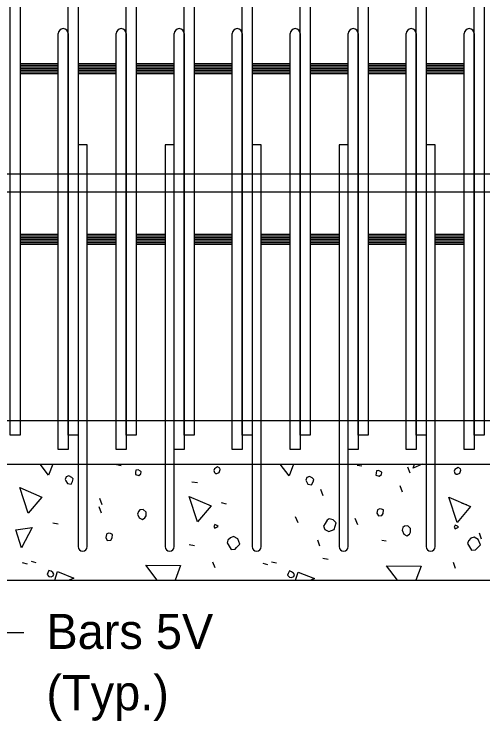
# Model space of a CAD drawing. Extents: x 120588.1 to 120659.6, y 120683.4 to 120715.5.
# Drawn here: x 120592.421 to 120595.115, y 120694.946 to 120699.004 of the extents above; entities that cross this region are included whole.
import ezdxf

# ---------------------------------------------------------------- set-up
doc = ezdxf.new("R2010")
doc.units = 0
for name, color, linetype in [('Dimension', 7, 'Continuous'), ('SheetBorder_dp', 7, 'Continuous'), ('SheetLines_dp', 7, 'Continuous'), ('SupstrConc', 7, 'Continuous')]:
    doc.layers.add(name, color=color, linetype=linetype)

msp = doc.modelspace()

# ---------------------------------------------------------------- linework, layer by layer
at = {"layer": 'Dimension'}
for p, q in [((120593.0102, 120696.4184), (120593.0367, 120696.4131)), ((120594.3926, 120696.4148), (120594.4191, 120696.4095)), ((120594.6966, 120696.3689), (120594.6843, 120696.4024)), ((120593.4433, 120696.3176), (120593.4751, 120696.3141)), ((120594.1979, 120696.2387), (120594.1837, 120696.2741)), ((120594.6542, 120696.2593), (120594.6401, 120696.2946)), ((120592.9271, 120696.1868), (120592.913, 120696.2221)), ((120593.6112, 120696.1992), (120593.6395, 120696.1921)), ((120594.9936, 120696.1956), (120595.0219, 120696.1885)), ((120592.924, 120696.1389), (120592.9099, 120696.1743)), ((120594.0532, 120696.0825), (120594.039, 120696.1178)), ((120594.3961, 120696.0719), (120594.382, 120696.1072)), ((120592.6442, 120696.0831), (120592.6742, 120696.0778)), ((120595.1079, 120695.99), (120595.0956, 120696.0236)), ((120594.1787, 120695.9499), (120594.1663, 120695.9835)), ((120594.534, 120695.9835), (120594.5588, 120695.9799)), ((120593.4274, 120695.9587), (120593.4574, 120695.9534)), ((120592.5188, 120695.8633), (120592.547, 120695.8562)), ((120594.1964, 120695.8792), (120594.2264, 120695.8739)), ((120592.4675, 120695.8544), (120592.4958, 120695.8474)), ((120593.5759, 120695.8244), (120593.5635, 120695.858)), ((120593.8499, 120695.8509), (120593.8782, 120695.8438)), ((120593.9012, 120695.8597), (120593.9294, 120695.8527)), ((120594.9583, 120695.8208), (120594.9459, 120695.8544))]:
    msp.add_line(p, q, dxfattribs=at)
for points in [[(120592.6195, 120696.3565), (120592.571, 120696.4203)], [(120592.6434, 120696.4203), (120592.6195, 120696.3565)], [(120593.5794, 120696.3653), (120593.5865, 120696.3653), (120593.6006, 120696.3724), (120593.6059, 120696.3883), (120593.6042, 120696.3971), (120593.59, 120696.4042), (120593.5723, 120696.3936), (120593.5688, 120696.383), (120593.5723, 120696.3724), (120593.5794, 120696.3653)], [(120594.0019, 120696.3529), (120593.9507, 120696.4203)], [(120594.0271, 120696.4203), (120594.0019, 120696.3529)], [(120594.7143, 120696.3971), (120594.7215, 120696.4203)], [(120594.766, 120696.4203), (120594.7143, 120696.3971)], [(120594.9618, 120696.3618), (120594.9689, 120696.3618), (120594.983, 120696.3689), (120594.9883, 120696.3848), (120594.9866, 120696.3936), (120594.9724, 120696.4007), (120594.9547, 120696.3901), (120594.9512, 120696.3795), (120594.9547, 120696.3689), (120594.9618, 120696.3618)], [(120592.7185, 120696.3247), (120592.7274, 120696.3088), (120592.7486, 120696.3052), (120592.7574, 120696.3211), (120592.7609, 120696.3353), (120592.7521, 120696.3441), (120592.7362, 120696.3529), (120592.7203, 120696.3476), (120592.715, 120696.3317), (120592.7185, 120696.3247)], [(120593.118, 120696.36), (120593.1375, 120696.3547), (120593.1499, 120696.3636), (120593.1516, 120696.3759), (120593.1481, 120696.3795), (120593.1339, 120696.3865), (120593.1216, 120696.3848), (120593.1198, 120696.3724), (120593.118, 120696.36)], [(120594.1009, 120696.3211), (120594.1097, 120696.3052), (120594.131, 120696.3017), (120594.1398, 120696.3176), (120594.1433, 120696.3317), (120594.1345, 120696.3406), (120594.1186, 120696.3494), (120594.1027, 120696.3441), (120594.0974, 120696.3282), (120594.1009, 120696.3211)], [(120594.5004, 120696.3565), (120594.5199, 120696.3512), (120594.5322, 120696.36), (120594.534, 120696.3724), (120594.5305, 120696.3759), (120594.5163, 120696.383), (120594.504, 120696.3812), (120594.5022, 120696.3689), (120594.5004, 120696.3565)], [(120592.5022, 120696.1383), (120592.4544, 120696.285), (120592.5799, 120696.2302), (120592.5022, 120696.1383)], [(120593.4751, 120696.0878), (120593.4274, 120696.2345), (120593.5529, 120696.1797), (120593.4751, 120696.0878)], [(120594.9668, 120696.0842), (120594.919, 120696.231), (120595.0445, 120696.1762), (120594.9668, 120696.0842)], [(120593.1299, 120696.1331), (120593.1406, 120696.1119), (120593.1582, 120696.1012), (120593.1724, 120696.1119), (120593.1794, 120696.1225), (120593.1794, 120696.1437), (120593.1635, 120696.1596), (120593.1441, 120696.1578), (120593.1353, 120696.149), (120593.1299, 120696.1331)], [(120594.5057, 120696.139), (120594.5146, 120696.1231), (120594.534, 120696.1249), (120594.5429, 120696.1373), (120594.5446, 120696.1567), (120594.5322, 120696.162), (120594.5234, 120696.1638), (120594.5128, 120696.1603), (120594.5093, 120696.1567), (120594.5057, 120696.139)], [(120594.207, 120696.0454), (120594.23, 120696.033), (120594.26, 120696.0454), (120594.2724, 120696.0825), (120594.2547, 120696.1002), (120594.2317, 120696.1055), (120594.2211, 120696.0984), (120594.2087, 120696.0789), (120594.1999, 120696.063), (120594.207, 120696.0454)], [(120593.5741, 120696.0524), (120593.5936, 120696.0613), (120593.5865, 120696.0683), (120593.5741, 120696.0736), (120593.5688, 120696.0613), (120593.5741, 120696.0524)], [(120594.6507, 120696.0401), (120594.6613, 120696.0188), (120594.679, 120696.0082), (120594.6931, 120696.0188), (120594.7002, 120696.0294), (120594.7002, 120696.0507), (120594.6843, 120696.0666), (120594.6648, 120696.0648), (120594.656, 120696.056), (120594.6507, 120696.0401)], [(120594.9565, 120696.0489), (120594.976, 120696.0577), (120594.9689, 120696.0648), (120594.9565, 120696.0701), (120594.9512, 120696.0577), (120594.9565, 120696.0489)], [(120592.464, 120695.9393), (120592.4304, 120696.0436), (120592.5241, 120696.056), (120592.464, 120695.9393)], [(120592.9479, 120695.9983), (120592.9568, 120695.9824), (120592.9762, 120695.9842), (120592.9851, 120695.9965), (120592.9868, 120696.016), (120592.9745, 120696.0213), (120592.9656, 120696.0231), (120592.955, 120696.0195), (120592.9515, 120696.016), (120592.9479, 120695.9983)], [(120593.6448, 120695.9676), (120593.6678, 120695.9305), (120593.6908, 120695.9322), (120593.6996, 120695.9411), (120593.7191, 120695.9605), (120593.7067, 120695.9906), (120593.6819, 120696.0047), (120593.6643, 120695.9976), (120593.6501, 120695.9835), (120593.6448, 120695.9676)], [(120595.0272, 120695.964), (120595.0502, 120695.9269), (120595.0732, 120695.9287), (120595.082, 120695.9375), (120595.1015, 120695.957), (120595.0891, 120695.987), (120595.0643, 120696.0012), (120595.0467, 120695.9941), (120595.0325, 120695.9799), (120595.0272, 120695.964)], [(120593.244, 120695.7537), (120593.1781, 120695.8403), (120593.3779, 120695.8385), (120593.3462, 120695.7537)], [(120594.6237, 120695.7537), (120594.5605, 120695.8368), (120594.7603, 120695.835), (120594.7299, 120695.7537)], [(120592.6213, 120695.7749), (120592.6337, 120695.7731), (120592.646, 120695.7784), (120592.6496, 120695.789), (120592.6443, 120695.7979), (120592.6337, 120695.8049), (120592.6213, 120695.8102), (120592.6142, 120695.7961), (120592.6107, 120695.7855), (120592.6213, 120695.7749)], [(120592.6556, 120695.7537), (120592.6708, 120695.8032), (120592.7645, 120695.766), (120592.7369, 120695.7537)], [(120594.0037, 120695.7714), (120594.0161, 120695.7696), (120594.0284, 120695.7749), (120594.032, 120695.7855), (120594.0267, 120695.7943), (120594.0161, 120695.8014), (120594.0037, 120695.8067), (120593.9966, 120695.7926), (120593.9931, 120695.782), (120594.0037, 120695.7714)], [(120594.039, 120695.7537), (120594.0532, 120695.7996), (120594.1469, 120695.7625), (120594.1272, 120695.7537)]]:
    msp.add_lwpolyline(points, dxfattribs=at)
at = {"layer": 'SheetBorder_dp'}
for p, q in [((120588.5208, 120698.087), (120598.0015, 120698.087)), ((120588.5208, 120697.9829), (120598.0015, 120697.9829)), ((120588.5208, 120696.6703), (120598.0015, 120696.6703)), ((120588.5208, 120696.4203), (120607.6672, 120696.4203)), ((120588.5208, 120695.7537), (120607.6672, 120695.7537))]:
    msp.add_line(p, q, dxfattribs=at)
at = {"layer": 'SheetLines_dp'}
msp.add_open_spline([(120592.4772, 120695.4523), (120592.2948, 120695.4435), (120592.0006, 120695.5358), (120592.1255, 120696.1436), (120591.3414, 120696.2866)], degree=2, dxfattribs=at)
at = {"layer": 'SupstrConc'}
for p, q in [((120592.6747, 120696.5037), (120592.6747, 120698.8917)), ((120592.732, 120698.8917), (120592.732, 120696.5037)), ((120593.008, 120696.5037), (120593.008, 120698.8917)), ((120593.0653, 120698.8917), (120593.0653, 120696.5037)), ((120593.3414, 120696.5037), (120593.3414, 120698.8917)), ((120593.3987, 120698.8917), (120593.3987, 120696.5037)), ((120593.6747, 120696.5037), (120593.6747, 120698.8917)), ((120593.732, 120698.8917), (120593.732, 120696.5037)), ((120594.008, 120696.5037), (120594.008, 120698.8917)), ((120594.0653, 120698.8917), (120594.0653, 120696.5037)), ((120594.3414, 120696.5037), (120594.3414, 120698.8917)), ((120594.3987, 120698.8917), (120594.3987, 120696.5037)), ((120594.6747, 120696.5037), (120594.6747, 120698.8917)), ((120594.732, 120698.8917), (120594.732, 120696.5037)), ((120595.008, 120696.5037), (120595.008, 120698.8917)), ((120595.0653, 120698.8917), (120595.0653, 120696.5037)), ((120592.456, 120698.7198), (120592.6747, 120698.7198)), ((120592.456, 120698.7102), (120592.6747, 120698.7102)), ((120592.456, 120698.7007), (120592.6747, 120698.7007)), ((120592.7893, 120698.7198), (120593.008, 120698.7198)), ((120592.7893, 120698.7102), (120593.008, 120698.7102)), ((120592.7893, 120698.7007), (120593.008, 120698.7007)), ((120593.1226, 120698.7198), (120593.3414, 120698.7198)), ((120593.1226, 120698.7102), (120593.3414, 120698.7102)), ((120593.1226, 120698.7007), (120593.3414, 120698.7007)), ((120593.456, 120698.7198), (120593.6747, 120698.7198)), ((120593.456, 120698.7102), (120593.6747, 120698.7102)), ((120593.456, 120698.7007), (120593.6747, 120698.7007)), ((120593.7893, 120698.7198), (120594.008, 120698.7198)), ((120593.7893, 120698.7102), (120594.008, 120698.7102)), ((120593.7893, 120698.7007), (120594.008, 120698.7007)), ((120594.1226, 120698.7198), (120594.3414, 120698.7198)), ((120594.1226, 120698.7102), (120594.3414, 120698.7102)), ((120594.1226, 120698.7007), (120594.3414, 120698.7007)), ((120594.456, 120698.7198), (120594.6747, 120698.7198)), ((120594.456, 120698.7102), (120594.6747, 120698.7102)), ((120594.456, 120698.7007), (120594.6747, 120698.7007)), ((120594.7893, 120698.7198), (120595.008, 120698.7198)), ((120594.7893, 120698.7102), (120595.008, 120698.7102)), ((120594.7893, 120698.7007), (120595.008, 120698.7007)), ((120592.456, 120698.6911), (120592.6747, 120698.6911)), ((120592.456, 120698.6816), (120592.6747, 120698.6816)), ((120592.456, 120698.672), (120592.6747, 120698.672)), ((120592.456, 120698.6625), (120592.6747, 120698.6625)), ((120592.7893, 120698.6911), (120593.008, 120698.6911)), ((120592.7893, 120698.6816), (120593.008, 120698.6816)), ((120592.7893, 120698.672), (120593.008, 120698.672)), ((120592.7893, 120698.6625), (120593.008, 120698.6625)), ((120593.1226, 120698.6911), (120593.3414, 120698.6911)), ((120593.1226, 120698.6816), (120593.3414, 120698.6816)), ((120593.1226, 120698.672), (120593.3414, 120698.672)), ((120593.1226, 120698.6625), (120593.3414, 120698.6625)), ((120593.456, 120698.6911), (120593.6747, 120698.6911)), ((120593.456, 120698.6816), (120593.6747, 120698.6816)), ((120593.456, 120698.672), (120593.6747, 120698.672)), ((120593.456, 120698.6625), (120593.6747, 120698.6625)), ((120593.7893, 120698.6911), (120594.008, 120698.6911)), ((120593.7893, 120698.6816), (120594.008, 120698.6816)), ((120593.7893, 120698.672), (120594.008, 120698.672)), ((120593.7893, 120698.6625), (120594.008, 120698.6625)), ((120594.1226, 120698.6911), (120594.3414, 120698.6911)), ((120594.1226, 120698.6816), (120594.3414, 120698.6816)), ((120594.1226, 120698.672), (120594.3414, 120698.672)), ((120594.1226, 120698.6625), (120594.3414, 120698.6625)), ((120594.456, 120698.6911), (120594.6747, 120698.6911)), ((120594.456, 120698.6816), (120594.6747, 120698.6816)), ((120594.456, 120698.672), (120594.6747, 120698.672)), ((120594.456, 120698.6625), (120594.6747, 120698.6625)), ((120594.7893, 120698.6911), (120595.008, 120698.6911)), ((120594.7893, 120698.6816), (120595.008, 120698.6816)), ((120594.7893, 120698.672), (120595.008, 120698.672)), ((120594.7893, 120698.6625), (120595.008, 120698.6625)), ((120592.8414, 120698.2537), (120592.7893, 120698.2537)), ((120592.7893, 120698.2537), (120592.7893, 120695.9464)), ((120592.8414, 120695.9464), (120592.8414, 120698.2537)), ((120593.3414, 120698.2537), (120593.2893, 120698.2537)), ((120593.2893, 120698.2537), (120593.2893, 120695.9464)), ((120593.3414, 120695.9464), (120593.3414, 120698.2537)), ((120593.8414, 120698.2537), (120593.7893, 120698.2537)), ((120593.7893, 120698.2537), (120593.7893, 120695.9464)), ((120593.8414, 120695.9464), (120593.8414, 120698.2537)), ((120594.3414, 120698.2537), (120594.2893, 120698.2537)), ((120594.2893, 120698.2537), (120594.2893, 120695.9464)), ((120594.3414, 120695.9464), (120594.3414, 120698.2537)), ((120594.8414, 120698.2537), (120594.7893, 120698.2537)), ((120594.7893, 120698.2537), (120594.7893, 120695.9464)), ((120594.8414, 120695.9464), (120594.8414, 120698.2537)), ((120592.456, 120697.7406), (120592.6747, 120697.7406)), ((120592.456, 120697.7311), (120592.6747, 120697.7311)), ((120592.8414, 120697.7406), (120593.008, 120697.7406)), ((120592.8414, 120697.7311), (120593.008, 120697.7311)), ((120593.1226, 120697.7406), (120593.2893, 120697.7406)), ((120593.1226, 120697.7311), (120593.2893, 120697.7311)), ((120593.456, 120697.7406), (120593.6747, 120697.7406)), ((120593.456, 120697.7311), (120593.6747, 120697.7311)), ((120593.8414, 120697.7406), (120594.008, 120697.7406)), ((120593.8414, 120697.7311), (120594.008, 120697.7311)), ((120594.1226, 120697.7406), (120594.2893, 120697.7406)), ((120594.1226, 120697.7311), (120594.2893, 120697.7311)), ((120594.456, 120697.7406), (120594.6747, 120697.7406)), ((120594.456, 120697.7311), (120594.6747, 120697.7311)), ((120594.8414, 120697.7406), (120595.008, 120697.7406)), ((120594.8414, 120697.7311), (120595.008, 120697.7311)), ((120592.456, 120697.7215), (120592.6747, 120697.7215)), ((120592.456, 120697.712), (120592.6747, 120697.712)), ((120592.456, 120697.7024), (120592.6747, 120697.7024)), ((120592.456, 120697.6929), (120592.6747, 120697.6929)), ((120592.8414, 120697.7215), (120593.008, 120697.7215)), ((120592.8414, 120697.712), (120593.008, 120697.712)), ((120592.8414, 120697.7024), (120593.008, 120697.7024)), ((120592.8414, 120697.6929), (120593.008, 120697.6929)), ((120593.1226, 120697.7215), (120593.2893, 120697.7215)), ((120593.1226, 120697.712), (120593.2893, 120697.712)), ((120593.1226, 120697.7024), (120593.2893, 120697.7024)), ((120593.1226, 120697.6929), (120593.2893, 120697.6929)), ((120593.456, 120697.7215), (120593.6747, 120697.7215)), ((120593.456, 120697.712), (120593.6747, 120697.712)), ((120593.456, 120697.7024), (120593.6747, 120697.7024)), ((120593.456, 120697.6929), (120593.6747, 120697.6929)), ((120593.8414, 120697.7215), (120594.008, 120697.7215)), ((120593.8414, 120697.712), (120594.008, 120697.712)), ((120593.8414, 120697.7024), (120594.008, 120697.7024)), ((120593.8414, 120697.6929), (120594.008, 120697.6929)), ((120594.1226, 120697.7215), (120594.2893, 120697.7215)), ((120594.1226, 120697.712), (120594.2893, 120697.712)), ((120594.1226, 120697.7024), (120594.2893, 120697.7024)), ((120594.1226, 120697.6929), (120594.2893, 120697.6929)), ((120594.456, 120697.7215), (120594.6747, 120697.7215)), ((120594.456, 120697.712), (120594.6747, 120697.712)), ((120594.456, 120697.7024), (120594.6747, 120697.7024)), ((120594.456, 120697.6929), (120594.6747, 120697.6929)), ((120594.8414, 120697.7215), (120595.008, 120697.7215)), ((120594.8414, 120697.712), (120595.008, 120697.712)), ((120594.8414, 120697.7024), (120595.008, 120697.7024)), ((120594.8414, 120697.6929), (120595.008, 120697.6929)), ((120592.456, 120697.6833), (120592.6747, 120697.6833)), ((120592.8414, 120697.6833), (120593.008, 120697.6833)), ((120593.1226, 120697.6833), (120593.2893, 120697.6833)), ((120593.456, 120697.6833), (120593.6747, 120697.6833)), ((120593.8414, 120697.6833), (120594.008, 120697.6833)), ((120594.1226, 120697.6833), (120594.2893, 120697.6833)), ((120594.456, 120697.6833), (120594.6747, 120697.6833)), ((120594.8414, 120697.6833), (120595.008, 120697.6833)), ((120592.732, 120696.5037), (120592.6747, 120696.5037)), ((120593.0653, 120696.5037), (120593.008, 120696.5037)), ((120593.3987, 120696.5037), (120593.3414, 120696.5037)), ((120593.732, 120696.5037), (120593.6747, 120696.5037)), ((120594.0653, 120696.5037), (120594.008, 120696.5037)), ((120594.3987, 120696.5037), (120594.3414, 120696.5037)), ((120594.732, 120696.5037), (120594.6747, 120696.5037)), ((120595.0653, 120696.5037), (120595.008, 120696.5037))]:
    msp.add_line(p, q, dxfattribs=at)
for points in [[(120592.3987, 120704.2537), (120592.456, 120704.2537), (120592.456, 120696.587), (120592.3987, 120696.587)], [(120592.732, 120704.2537), (120592.7893, 120704.2537), (120592.7893, 120696.587), (120592.732, 120696.587)], [(120593.0653, 120704.2537), (120593.1226, 120704.2537), (120593.1226, 120696.587), (120593.0653, 120696.587)], [(120593.3987, 120704.2537), (120593.456, 120704.2537), (120593.456, 120696.587), (120593.3987, 120696.587)], [(120593.732, 120704.2537), (120593.7893, 120704.2537), (120593.7893, 120696.587), (120593.732, 120696.587)], [(120594.0653, 120704.2537), (120594.1226, 120704.2537), (120594.1226, 120696.587), (120594.0653, 120696.587)], [(120594.3987, 120704.2537), (120594.456, 120704.2537), (120594.456, 120696.587), (120594.3987, 120696.587)], [(120594.732, 120704.2537), (120594.7893, 120704.2537), (120594.7893, 120696.587), (120594.732, 120696.587)], [(120595.0653, 120704.2537), (120595.1226, 120704.2537), (120595.1226, 120696.587), (120595.0653, 120696.587)]]:
    msp.add_lwpolyline(points, close=True, dxfattribs=at)
for centre, radius, start, end in [((120592.7034, 120698.8917), 0.0286, 0, 180), ((120593.0367, 120698.8917), 0.0286, 0, 180), ((120593.37, 120698.8917), 0.0286, 0, 180), ((120593.7034, 120698.8917), 0.0286, 0, 180), ((120594.0367, 120698.8917), 0.0286, 0, 180), ((120594.37, 120698.8917), 0.0286, 0, 180), ((120594.7034, 120698.8917), 0.0286, 0, 180), ((120595.0367, 120698.8917), 0.0286, 0, 180), ((120592.8153, 120695.9464), 0.026, 180, 0), ((120593.3153, 120695.9464), 0.026, 180, 0), ((120593.8153, 120695.9464), 0.026, 180, 0), ((120594.3153, 120695.9464), 0.026, 180, 0), ((120594.8153, 120695.9464), 0.026, 180, 0)]:
    msp.add_arc(centre, radius, start, end, dxfattribs=at)

# ---------------------------------------------------------------- texts
at = {"layer": 'SheetLines_dp'}
for s, p in [('Bars 5V ', (120592.6069, 120695.3588)), ('(Typ.)', (120592.6069, 120695.0068))]:
    msp.add_text(s, height=0.2016, dxfattribs=at).set_placement(p)

doc.saveas('drawing.dxf')
